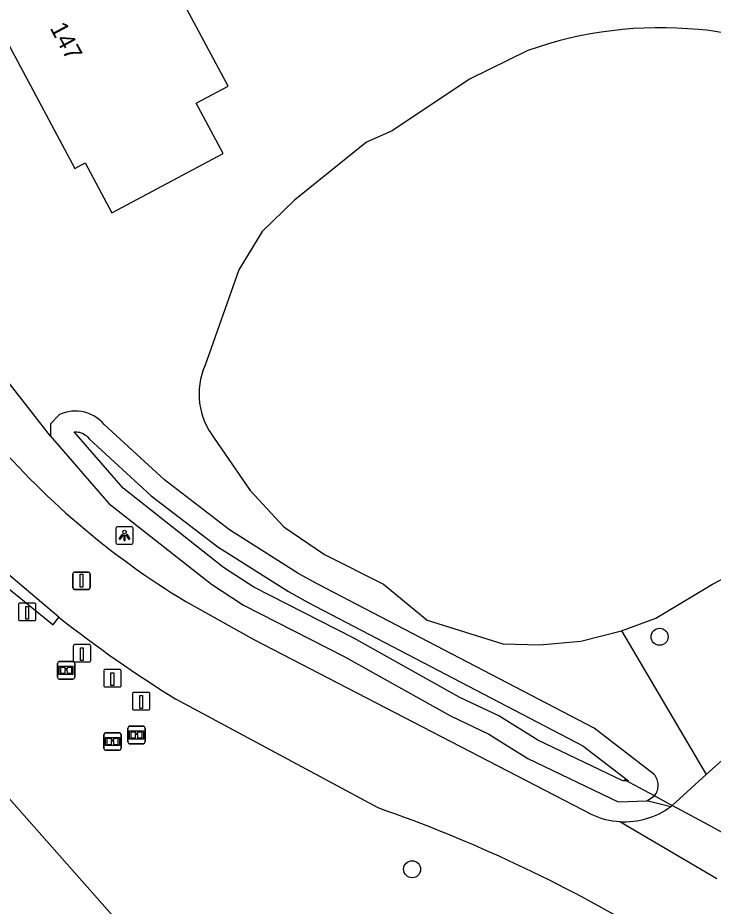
# Model space of a CAD drawing. Extents: x 160203 to 161526, y 379529 to 381797.
# Drawn here: x 160798.6 to 160838.5, y 381481.5 to 381532.5 of the extents above; entities that cross this region are included whole.
import ezdxf

# ---------------------------------------------------------------- set-up
doc = ezdxf.new("R2010")
doc.units = 0
for name, color, linetype in [('IMGEO_Afsluitpaal', 7, 'Continuous'), ('IMGEO_Boom', 7, 'Continuous'), ('IMGEO_Duiker', 7, 'Continuous'), ('IMGEO_Fietspad_gesloten', 7, 'Continuous'), ('IMGEO_Gemengd_bos', 7, 'Continuous'), ('IMGEO_Groenvoorziening', 7, 'Continuous'), ('IMGEO_Hek', 7, 'Continuous'), ('IMGEO_Informatiebord', 7, 'Continuous'), ('IMGEO_Lichtpunt', 7, 'Continuous'), ('IMGEO_Loofbos', 7, 'Continuous'), ('IMGEO_Meer_plas_ven_vijver', 7, 'Continuous'), ('IMGEO_Paal', 7, 'Continuous'), ('IMGEO_Pand', 7, 'Continuous'), ('IMGEO_Pand_nummerreeks', 7, 'Continuous'), ('IMGEO_Rijbaan_lokaal_gesloten', 7, 'Continuous'), ('IMGEO_Verkeerseiland_open', 7, 'Continuous'), ('IMGEO_Waterloop', 7, 'Continuous')]:
    doc.layers.add(name, color=color, linetype=linetype)

msp = doc.modelspace()

# ---------------------------------------------------------------- linework, layer by layer
at = {"layer": 'IMGEO_Afsluitpaal'}
for p, q in [((160801.741, 381499.801), (160801.741, 381500.601)), ((160801.741, 381500.601), (160801.741, 381499.801)), ((160801.841, 381500.701), (160802.631, 381500.701)), ((160802.631, 381500.701), (160801.841, 381500.701)), ((160802.731, 381500.601), (160802.731, 381499.801)), ((160802.731, 381499.801), (160802.731, 381500.601)), ((160802.631, 381499.701), (160801.841, 381499.701)), ((160801.841, 381499.701), (160802.631, 381499.701))]:
    msp.add_line(p, q, dxfattribs=at)
msp.add_lwpolyline([(160802.161, 381500.576), (160802.311, 381500.576), (160802.311, 381499.826), (160802.161, 381499.826), (160802.161, 381500.576)], dxfattribs=at)
for centre, start, end in [((160801.841, 381500.601), 90, 180), ((160801.841, 381500.601), 90, 180), ((160802.631, 381500.601), 0, 90), ((160802.631, 381500.601), 360, 90), ((160801.841, 381499.801), 180, 270), ((160801.841, 381499.801), 180, 270), ((160802.631, 381499.801), 270, 0), ((160802.631, 381499.801), 270, 0)]:
    msp.add_arc(centre, 0.1, start, end, dxfattribs=at)
at = {"layer": 'IMGEO_Boom'}
for centre in [(160835.414, 381496.987), (160821.211, 381483.648)]:
    msp.add_circle(centre, 0.489, dxfattribs=at)
at = {"layer": 'IMGEO_Duiker'}
msp.add_lwpolyline([(160840.396, 381485.007), (160839.072, 381485.721), (160838.956, 381485.784), (160838.229, 381486.176), (160836.129, 381487.309), (160835.95, 381487.405), (160835.112, 381487.857), (160833.402, 381488.78)], dxfattribs=at)
at = {"layer": 'IMGEO_Fietspad_gesloten'}
for points in [[(160848.596, 381500.189), (160848.431, 381500), (160844.567, 381495.576), (160840.563, 381491.311), (160838.084, 381489.081)], [(160838.084, 381489.081), (160836.129, 381487.309), (160836.051, 381487.238)]]:
    msp.add_lwpolyline(points, dxfattribs=at)
msp.add_arc((160833.415, 381490.821), 4.448, 266.3011, 306.3442, dxfattribs=at)
at = {"layer": 'IMGEO_Gemengd_bos'}
msp.add_lwpolyline([(160833.223, 381497.318), (160838.084, 381489.081)], dxfattribs=at)
at = {"layer": 'IMGEO_Groenvoorziening'}
for points in [[(160834.687, 381487.571), (160835.112, 381487.857), (160835.163, 381487.923), (160835.209, 381487.994), (160835.247, 381488.069), (160835.279, 381488.147), (160835.304, 381488.227), (160835.321, 381488.309), (160835.332, 381488.392), (160835.334, 381488.476), (160835.329, 381488.56), (160835.317, 381488.643), (160835.297, 381488.725), (160835.27, 381488.804), (160835.236, 381488.881), (160835.196, 381488.955), (160835.149, 381489.024), (160835.096, 381489.089), (160835.084, 381489.102), (160831.653, 381491.738), (160815.804, 381500), (160814.718, 381500.604), (160810.738, 381503.122), (160806.999, 381505.985), (160803.531, 381509.171), (160803.403, 381509.311), (160803.263, 381509.44), (160803.112, 381509.555), (160802.952, 381509.657), (160802.783, 381509.743), (160802.607, 381509.815), (160802.425, 381509.87), (160802.239, 381509.909), (160802.051, 381509.931), (160801.861, 381509.936), (160801.671, 381509.924), (160801.484, 381509.895), (160801.299, 381509.85), (160801.12, 381509.788), (160800.946, 381509.711), (160800.933, 381509.704), (160800.45, 381509.197), (160800.467, 381508.496)], [(160811.474, 381472.566), (160806.02, 381478.729), (160794.451, 381491.803), (160790.399, 381495.985), (160780.387, 381484.943)]]:
    msp.add_lwpolyline(points, dxfattribs=at)
at = {"layer": 'IMGEO_Hek'}
msp.add_lwpolyline([(160794.451, 381491.803), (160806.02, 381478.729), (160806.164, 381478.403), (160806.229, 381478.256), (160809.639, 381470.557), (160813.749, 381475.058), (160817.52, 381478.04), (160829.705, 381476.805), (160839.451, 381471.923)], dxfattribs=at)
at = {"layer": 'IMGEO_Informatiebord'}
for p, q in [((160800.859, 381494.662), (160800.859, 381495.462)), ((160800.859, 381495.462), (160800.859, 381494.662)), ((160800.959, 381495.562), (160801.749, 381495.562)), ((160801.749, 381495.562), (160800.959, 381495.562)), ((160801.849, 381495.462), (160801.849, 381494.662)), ((160801.849, 381494.662), (160801.849, 381495.462)), ((160801.749, 381494.562), (160800.959, 381494.562)), ((160800.959, 381494.562), (160801.749, 381494.562)), ((160805.001, 381491.852), (160805.791, 381491.852)), ((160805.791, 381491.852), (160805.001, 381491.852)), ((160803.523, 381490.574), (160803.523, 381491.374)), ((160803.523, 381491.374), (160803.523, 381490.574)), ((160803.623, 381491.474), (160804.413, 381491.474)), ((160804.413, 381491.474), (160803.623, 381491.474)), ((160804.513, 381491.374), (160804.513, 381490.574)), ((160804.513, 381490.574), (160804.513, 381491.374)), ((160804.901, 381490.952), (160804.901, 381491.752)), ((160804.901, 381491.752), (160804.901, 381490.952)), ((160805.891, 381491.752), (160805.891, 381490.952)), ((160805.891, 381490.952), (160805.891, 381491.752)), ((160805.791, 381490.852), (160805.001, 381490.852)), ((160805.001, 381490.852), (160805.791, 381490.852)), ((160804.413, 381490.474), (160803.623, 381490.474)), ((160803.623, 381490.474), (160804.413, 381490.474))]:
    msp.add_line(p, q, dxfattribs=at)
for points in [[(160800.96, 381495.294), (160801.748, 381495.294), (160801.748, 381494.83), (160800.96, 381494.83), (160800.96, 381495.294)], [(160801.025, 381495.229), (160801.025, 381494.895), (160801.3, 381494.895), (160801.301, 381495.108), (160801.405, 381495.109), (160801.406, 381494.895), (160801.683, 381494.895), (160801.683, 381495.229), (160801.407, 381495.229), (160801.407, 381495.149), (160801.301, 381495.149), (160801.301, 381495.229), (160801.025, 381495.229)], [(160805.002, 381491.584), (160805.79, 381491.584), (160805.79, 381491.12), (160805.002, 381491.12), (160805.002, 381491.584)], [(160805.067, 381491.519), (160805.067, 381491.185), (160805.342, 381491.185), (160805.343, 381491.398), (160805.447, 381491.399), (160805.448, 381491.185), (160805.725, 381491.185), (160805.725, 381491.519), (160805.449, 381491.519), (160805.449, 381491.439), (160805.343, 381491.439), (160805.343, 381491.519), (160805.067, 381491.519)], [(160803.624, 381491.206), (160804.412, 381491.206), (160804.412, 381490.742), (160803.624, 381490.742), (160803.624, 381491.206)], [(160803.689, 381491.141), (160803.689, 381490.807), (160803.964, 381490.807), (160803.965, 381491.02), (160804.069, 381491.021), (160804.07, 381490.807), (160804.347, 381490.807), (160804.347, 381491.141), (160804.071, 381491.141), (160804.071, 381491.061), (160803.965, 381491.061), (160803.965, 381491.141), (160803.689, 381491.141)]]:
    msp.add_lwpolyline(points, dxfattribs=at)
for centre, start, end in [((160800.959, 381495.462), 90, 180), ((160800.959, 381495.462), 90, 180), ((160801.749, 381495.462), 0, 90), ((160801.749, 381495.462), 360, 90), ((160800.959, 381494.662), 180, 270), ((160800.959, 381494.662), 180, 270), ((160801.749, 381494.662), 270, 0), ((160801.749, 381494.662), 270, 0), ((160805.001, 381491.752), 90, 180), ((160805.001, 381491.752), 90, 180), ((160805.791, 381491.752), 0, 90), ((160805.791, 381491.752), 360, 90), ((160803.623, 381491.374), 90, 180), ((160803.623, 381491.374), 90, 180), ((160804.413, 381491.374), 0, 90), ((160804.413, 381491.374), 360, 90), ((160805.001, 381490.952), 180, 270), ((160805.001, 381490.952), 180, 270), ((160805.791, 381490.952), 270, 0), ((160805.791, 381490.952), 270, 0), ((160803.623, 381490.574), 180, 270), ((160803.623, 381490.574), 180, 270), ((160804.413, 381490.574), 270, 0), ((160804.413, 381490.574), 270, 0)]:
    msp.add_arc(centre, 0.1, start, end, dxfattribs=at)
at = {"layer": 'IMGEO_Lichtpunt'}
for p, q in [((160804.208, 381503.201), (160804.208, 381502.394)), ((160804.208, 381503.201), (160804.208, 381502.394)), ((160805.11, 381503.296), (160804.302, 381503.296)), ((160805.11, 381503.296), (160804.302, 381503.296)), ((160805.204, 381502.394), (160805.204, 381503.201)), ((160805.204, 381502.394), (160805.204, 381503.201)), ((160804.302, 381502.3), (160805.11, 381502.3)), ((160804.302, 381502.3), (160805.11, 381502.3))]:
    msp.add_line(p, q, dxfattribs=at)
for points in [[(160804.582, 381502.865), (160804.621, 381502.837), (160804.433, 381502.575), (160804.395, 381502.602), (160804.582, 381502.865)], [(160804.684, 381502.817), (160804.731, 381502.817), (160804.731, 381502.495), (160804.684, 381502.495), (160804.684, 381502.817)], [(160804.794, 381502.837), (160804.832, 381502.864), (160805.019, 381502.602), (160804.98, 381502.574), (160804.794, 381502.837)]]:
    msp.add_lwpolyline(points, dxfattribs=at)
msp.add_circle((160804.707, 381502.999), 0.0994, dxfattribs=at)
for centre, start, end in [((160804.302, 381503.201), 90, 180), ((160804.302, 381503.201), 90, 180), ((160805.11, 381503.201), 0, 90), ((160805.11, 381503.201), 0, 90), ((160804.302, 381502.394), 180, 270), ((160804.302, 381502.394), 180, 270), ((160805.11, 381502.394), 270, 0), ((160805.11, 381502.394), 270, 360)]:
    msp.add_arc(centre, 0.0946, start, end, dxfattribs=at)
at = {"layer": 'IMGEO_Loofbos'}
for points in [[(160800.467, 381508.496), (160794.362, 381516.295), (160788.18, 381527.659)], [(160800.467, 381508.496), (160803.798, 381504.641), (160809.693, 381500), (160811.525, 381498.797), (160817.308, 381495.849), (160823.404, 381492.447), (160825.615, 381491.398), (160827.854, 381490.009), (160833.043, 381487.514), (160834.687, 381487.571)], [(160836.051, 381487.238), (160834.687, 381487.571)]]:
    msp.add_lwpolyline(points, dxfattribs=at)
at = {"layer": 'IMGEO_Meer_plas_ven_vijver'}
for points in [[(160827.846, 381530.621), (160824.507, 381528.98), (160820.063, 381526.02), (160818.586, 381525.358), (160814.456, 381522.028), (160812.598, 381520.237), (160811.259, 381518.031), (160809.327, 381512.568)], [(160809.86, 381508.372), (160811.925, 381505.374), (160813.842, 381503.292), (160816.188, 381501.71), (160819.56, 381500), (160822.071, 381497.947), (160826.409, 381496.586), (160828.535, 381496.529), (160830.888, 381496.728), (160833.223, 381497.318)], [(160833.223, 381497.318), (160835.197, 381498.06), (160838.455, 381500)]]:
    msp.add_lwpolyline(points, dxfattribs=at)
for centre, radius, start, end in [((160835.444, 381509.15), 22.776, 84.4731, 109.4888), ((160837.07, 381521.948), 9.889, 42.4584, 86.7095), ((160813.123, 381510.918), 4.139, 156.5111, 217.9675), ((160832.386, 381511.75), 13.225, 297.3162, 328.7986)]:
    msp.add_arc(centre, radius, start, end, dxfattribs=at)
at = {"layer": 'IMGEO_Paal'}
for p, q in [((160798.62, 381498.834), (160798.62, 381497.993)), ((160798.62, 381498.834), (160798.62, 381497.993)), ((160799.536, 381498.918), (160798.695, 381498.918)), ((160799.536, 381498.918), (160798.695, 381498.918)), ((160799.62, 381498.002), (160799.62, 381498.843)), ((160799.62, 381498.002), (160799.62, 381498.843)), ((160798.704, 381497.918), (160799.545, 381497.918)), ((160798.704, 381497.918), (160799.545, 381497.918)), ((160801.767, 381496.456), (160801.767, 381495.615)), ((160801.767, 381496.456), (160801.767, 381495.615)), ((160802.683, 381496.54), (160801.842, 381496.54)), ((160802.683, 381496.54), (160801.842, 381496.54)), ((160802.767, 381495.624), (160802.767, 381496.465)), ((160802.767, 381495.624), (160802.767, 381496.465)), ((160801.851, 381495.54), (160802.692, 381495.54)), ((160801.851, 381495.54), (160802.692, 381495.54)), ((160803.512, 381495.025), (160803.512, 381494.184)), ((160803.512, 381495.025), (160803.512, 381494.184)), ((160804.428, 381495.109), (160803.587, 381495.109)), ((160804.428, 381495.109), (160803.587, 381495.109)), ((160804.512, 381494.193), (160804.512, 381495.034)), ((160804.512, 381494.193), (160804.512, 381495.034)), ((160803.596, 381494.109), (160804.437, 381494.109)), ((160803.596, 381494.109), (160804.437, 381494.109)), ((160805.165, 381493.712), (160805.165, 381492.871)), ((160805.165, 381493.712), (160805.165, 381492.871)), ((160806.081, 381493.796), (160805.24, 381493.796)), ((160806.081, 381493.796), (160805.24, 381493.796)), ((160806.165, 381492.88), (160806.165, 381493.721)), ((160806.165, 381492.88), (160806.165, 381493.721)), ((160805.249, 381492.796), (160806.09, 381492.796)), ((160805.249, 381492.796), (160806.09, 381492.796))]:
    msp.add_line(p, q, dxfattribs=at)
for points in [[(160799.035, 381498.731), (160799.195, 381498.731), (160799.195, 381497.998), (160799.035, 381497.998), (160799.035, 381498.731)], [(160802.182, 381496.353), (160802.342, 381496.353), (160802.342, 381495.62), (160802.182, 381495.62), (160802.182, 381496.353)], [(160803.927, 381494.922), (160804.087, 381494.922), (160804.087, 381494.189), (160803.927, 381494.189), (160803.927, 381494.922)], [(160805.58, 381493.609), (160805.74, 381493.609), (160805.74, 381492.876), (160805.58, 381492.876), (160805.58, 381493.609)]]:
    msp.add_lwpolyline(points, dxfattribs=at)
for centre, start, end in [((160798.698, 381498.84), 92.4484, 184.2845), ((160798.698, 381498.84), 92.4484, 184.2845), ((160799.542, 381498.84), 2.4484, 94.2845), ((160799.542, 381498.84), 2.4484, 94.2845), ((160798.698, 381497.996), 182.4484, 274.2845), ((160798.698, 381497.996), 182.4484, 274.2845), ((160799.542, 381497.996), 272.4484, 4.2845), ((160799.542, 381497.996), 272.4484, 4.2845), ((160801.845, 381496.462), 92.4484, 184.2845), ((160801.845, 381496.462), 92.4484, 184.2845), ((160802.689, 381496.462), 2.4484, 94.2845), ((160802.689, 381496.462), 2.4484, 94.2845), ((160801.845, 381495.618), 182.4484, 274.2845), ((160801.845, 381495.618), 182.4484, 274.2845), ((160802.689, 381495.618), 272.4484, 4.2845), ((160802.689, 381495.618), 272.4484, 4.2845), ((160803.59, 381495.031), 92.4484, 184.2845), ((160803.59, 381495.031), 92.4484, 184.2845), ((160804.434, 381495.031), 2.4484, 94.2845), ((160804.434, 381495.031), 2.4484, 94.2845), ((160803.59, 381494.187), 182.4484, 274.2845), ((160803.59, 381494.187), 182.4484, 274.2845), ((160804.434, 381494.187), 272.4484, 4.2845), ((160804.434, 381494.187), 272.4484, 4.2845), ((160805.243, 381493.718), 92.4484, 184.2845), ((160805.243, 381493.718), 92.4484, 184.2845), ((160806.087, 381493.718), 2.4484, 94.2845), ((160806.087, 381493.718), 2.4484, 94.2845), ((160805.243, 381492.874), 182.4484, 274.2845), ((160805.243, 381492.874), 182.4484, 274.2845), ((160806.087, 381492.874), 272.4484, 4.2845), ((160806.087, 381492.874), 272.4484, 4.2845)]:
    msp.add_arc(centre, 0.0779, start, end, dxfattribs=at)
at = {"layer": 'IMGEO_Pand'}
msp.add_lwpolyline([(160808.824, 381527.591), (160810.651, 381528.569), (160804.516, 381540.034), (160795.717, 381535.325), (160801.852, 381523.86), (160802.452, 381524.181), (160803.988, 381521.309), (160810.361, 381524.719), (160808.824, 381527.591)], dxfattribs=at)
at = {"layer": 'IMGEO_Rijbaan_lokaal_gesloten'}
for points in [[(160800.937, 381498.104), (160798.062, 381500.537)], [(160808.221, 381499.01), (160812.118, 381496.835), (160831.524, 381486.793)], [(160819.263, 381487.166), (160807.659, 381493.402)], [(160833.128, 381486.382), (160838.705, 381483.124)]]:
    msp.add_lwpolyline(points, dxfattribs=at)
for centre, radius, start, end in [((160832.083, 381538.521), 46.158, 219.9783, 238.8708), ((160847.288, 381557.211), 75.113, 231.89718, 238.15769), ((160792.261, 381409.428), 82.293, 58.95172, 70.84561), ((160833.409, 381490.814), 4.441, 244.8839, 266.3722)]:
    msp.add_arc(centre, radius, start, end, dxfattribs=at)
at = {"layer": 'IMGEO_Verkeerseiland_open'}
msp.add_lwpolyline([(160798.062, 381500.537), (160797.637, 381500.098), (160800.616, 381497.665), (160800.937, 381498.104)], dxfattribs=at)
at = {"layer": 'IMGEO_Waterloop'}
msp.add_lwpolyline([(160833.624, 381488.724), (160833.513, 381488.72), (160833.294, 381488.713), (160828.427, 381491.053), (160826.185, 381492.444), (160823.949, 381493.505), (160817.868, 381496.898), (160812.123, 381499.827), (160810.388, 381500.966), (160804.623, 381505.505), (160801.826, 381508.742), (160801.883, 381508.746), (160801.966, 381508.744), (160802.047, 381508.734), (160802.13, 381508.717), (160802.209, 381508.693), (160802.287, 381508.661), (160802.361, 381508.623), (160802.431, 381508.579), (160802.498, 381508.528), (160802.56, 381508.471), (160802.688, 381508.33), (160806.234, 381505.073), (160810.057, 381502.145), (160814.111, 381499.581), (160815.24, 381498.953), (160831.011, 381490.732), (160833.624, 381488.724)], dxfattribs=at)

# ---------------------------------------------------------------- texts
at = {"layer": 'IMGEO_Pand_nummerreeks'}
msp.add_text('147', height=1, rotation=298.1515, dxfattribs=at).set_placement((160800.399, 381531.916))

doc.saveas('drawing.dxf')
